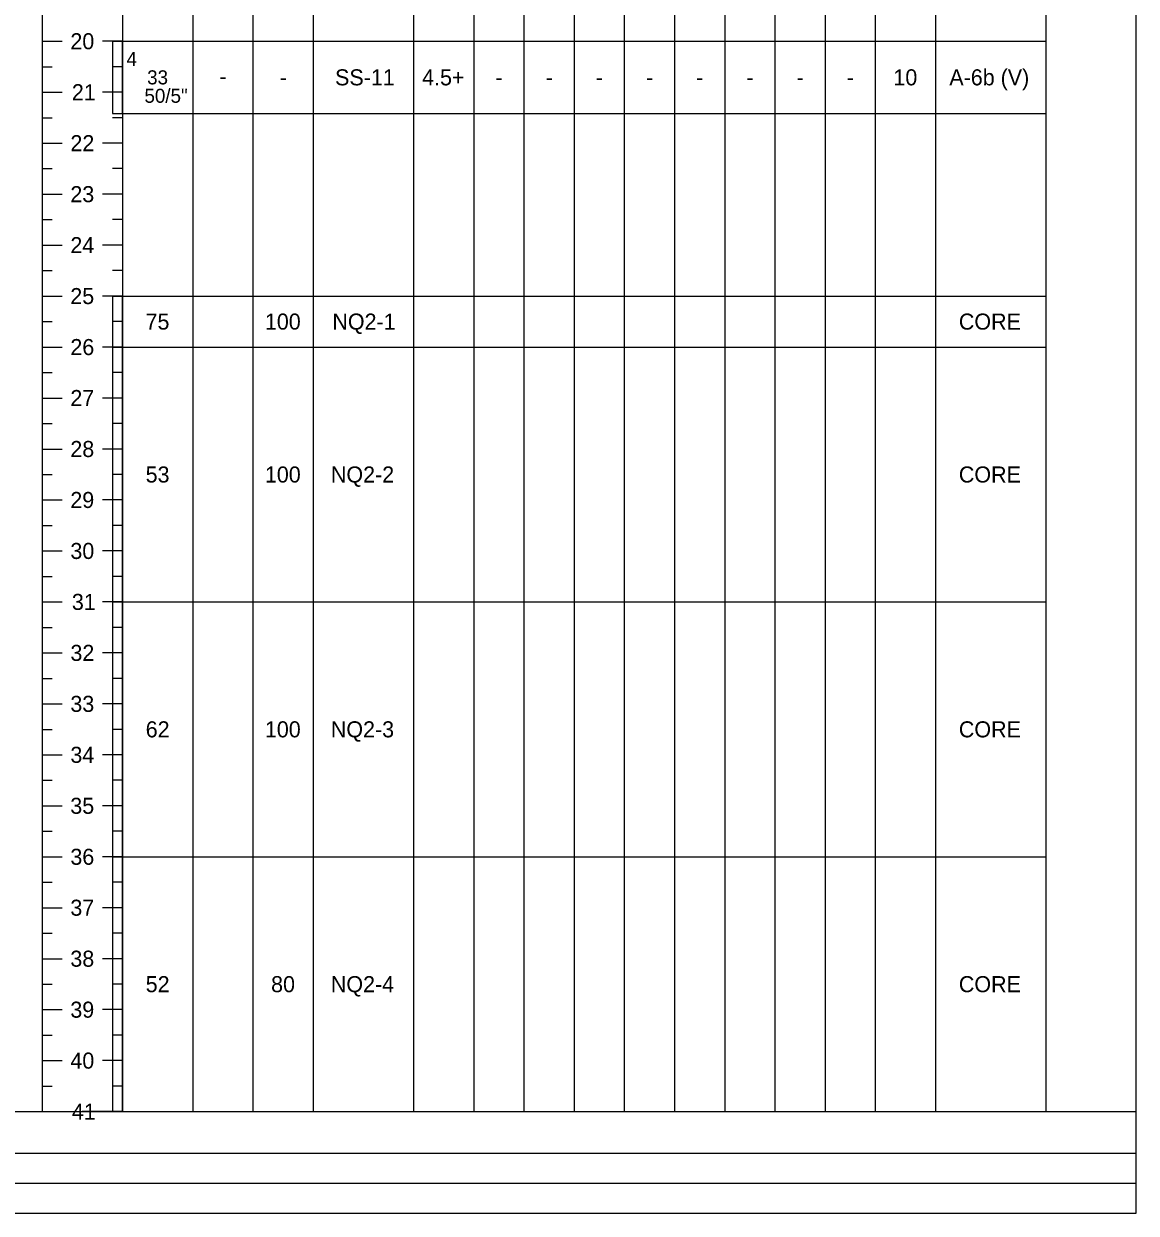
# Model space of a CAD drawing. Extents: x 0 to 0.833, y -0.381 to 0.608.
# Drawn here: x 0.3715 to 0.8333, y -0.3809 to 0.1131 of the extents above; entities that cross this region are included whole.
import ezdxf

# ---------------------------------------------------------------- set-up
doc = ezdxf.new("R2010")
doc.units = 0

msp = doc.modelspace()

# ---------------------------------------------------------------- linework, layer by layer
for points in [[(0, -0.38086), (0.83333, -0.38086), (0.83333, 0.60833), (0, 0.60833)], [(0.40833, 0.07585), (0.4125, 0.07585), (0.4125, 0.10583), (0.40833, 0.10583)], [(0.40833, -0.02117), (0.4125, -0.02117), (0.4125, 0), (0.40833, 0)], [(0.40833, -0.127), (0.4125, -0.127), (0.4125, -0.02117), (0.40833, -0.02117)], [(0.40833, -0.23283), (0.4125, -0.23283), (0.4125, -0.127), (0.40833, -0.127)], [(0.40833, -0.33867), (0.4125, -0.33867), (0.4125, -0.23283), (0.40833, -0.23283)]]:
    msp.add_lwpolyline(points, close=True)
for points in [[(0.4125, 0.55417), (0.4125, -0.33867)], [(0.4125, 0.55417), (0.4125, -0.33867)], [(0.44167, 0.55417), (0.44167, -0.33867)], [(0.46667, 0.55417), (0.46667, -0.33867)], [(0.49167, 0.55417), (0.49167, -0.33867)], [(0.53333, 0.55417), (0.53333, -0.33867)], [(0.55833, 0.55417), (0.55833, -0.33867)], [(0.6625, 0.55417), (0.6625, -0.33867)], [(0.725, 0.55417), (0.725, -0.33867)], [(0.75, 0.55417), (0.75, -0.33867)], [(0.75, 0.55417), (0.75, -0.33867)], [(0.79583, 0.55417), (0.79583, -0.33867)], [(0.57917, 0.54167), (0.57917, -0.33867)], [(0.6, 0.54167), (0.6, -0.33867)], [(0.62083, 0.54167), (0.62083, -0.33867)], [(0.64167, 0.54167), (0.64167, -0.33867)], [(0.68333, 0.54167), (0.68333, -0.33867)], [(0.70417, 0.54167), (0.70417, -0.33867)], [(0.725, 0.54167), (0.725, -0.33867)], [(0.37917, 0.52917), (0.37917, -0.33867)], [(0.37917, 0.10583), (0.3875, 0.10583)], [(0.37917, 0.10583), (0.38333, 0.10583)], [(0.4125, 0.10583), (0.40417, 0.10583)], [(0.40833, 0.10583), (0.40833, 0.07585)], [(0.40833, 0.10583), (0.4125, 0.10583)], [(0.4125, 0.10583), (0.40833, 0.10583)], [(0.4125, 0.10583), (0.44167, 0.10583)], [(0.44167, 0.10583), (0.46667, 0.10583)], [(0.46667, 0.10583), (0.49167, 0.10583)], [(0.49167, 0.10583), (0.53333, 0.10583)], [(0.53333, 0.10583), (0.55833, 0.10583)], [(0.55833, 0.10583), (0.57917, 0.10583)], [(0.57917, 0.10583), (0.6, 0.10583)], [(0.6, 0.10583), (0.62083, 0.10583)], [(0.62083, 0.10583), (0.64167, 0.10583)], [(0.64167, 0.10583), (0.6625, 0.10583)], [(0.6625, 0.10583), (0.68333, 0.10583)], [(0.68333, 0.10583), (0.70417, 0.10583)], [(0.70417, 0.10583), (0.725, 0.10583)], [(0.725, 0.10583), (0.75, 0.10583)], [(0.75, 0.10583), (0.79583, 0.10583)], [(0.37917, 0.09525), (0.38333, 0.09525)], [(0.4125, 0.09525), (0.40833, 0.09525)], [(0.37917, 0.08467), (0.3875, 0.08467)], [(0.37917, 0.08467), (0.38333, 0.08467)], [(0.4125, 0.08467), (0.40417, 0.08467)], [(0.4125, 0.08467), (0.40833, 0.08467)], [(0.40833, 0.07585), (0.4125, 0.07585)], [(0.4125, 0.07585), (0.44167, 0.07585)], [(0.44167, 0.07585), (0.46667, 0.07585)], [(0.46667, 0.07585), (0.49167, 0.07585)], [(0.49167, 0.07585), (0.53333, 0.07585)], [(0.53333, 0.07585), (0.55833, 0.07585)], [(0.55833, 0.07585), (0.57917, 0.07585)], [(0.57917, 0.07585), (0.6, 0.07585)], [(0.6, 0.07585), (0.62083, 0.07585)], [(0.62083, 0.07585), (0.64167, 0.07585)], [(0.64167, 0.07585), (0.6625, 0.07585)], [(0.6625, 0.07585), (0.68333, 0.07585)], [(0.68333, 0.07585), (0.70417, 0.07585)], [(0.70417, 0.07585), (0.725, 0.07585)], [(0.725, 0.07585), (0.75, 0.07585)], [(0.75, 0.07585), (0.79583, 0.07585)], [(0.37917, 0.07408), (0.38333, 0.07408)], [(0.4125, 0.07408), (0.40833, 0.07408)], [(0.37917, 0.0635), (0.3875, 0.0635)], [(0.37917, 0.0635), (0.38333, 0.0635)], [(0.4125, 0.0635), (0.40417, 0.0635)], [(0.4125, 0.0635), (0.40833, 0.0635)], [(0.37917, 0.05292), (0.38333, 0.05292)], [(0.4125, 0.05292), (0.40833, 0.05292)], [(0.37917, 0.04233), (0.3875, 0.04233)], [(0.37917, 0.04233), (0.38333, 0.04233)], [(0.4125, 0.04233), (0.40417, 0.04233)], [(0.4125, 0.04233), (0.40833, 0.04233)], [(0.37917, 0.03175), (0.38333, 0.03175)], [(0.4125, 0.03175), (0.40833, 0.03175)], [(0.37917, 0.02117), (0.3875, 0.02117)], [(0.37917, 0.02117), (0.38333, 0.02117)], [(0.4125, 0.02117), (0.40417, 0.02117)], [(0.4125, 0.02117), (0.40833, 0.02117)], [(0.37917, 0.01058), (0.38333, 0.01058)], [(0.4125, 0.01058), (0.40833, 0.01058)], [(0.37917, 0), (0.3875, 0)], [(0.37917, 0), (0.38333, 0)], [(0.4125, 0), (0.40417, 0)], [(0.40833, 0), (0.40833, -0.02117)], [(0.40833, 0), (0.4125, 0)], [(0.4125, 0), (0.40833, 0)], [(0.4125, 0), (0.44167, 0)], [(0.44167, 0), (0.46667, 0)], [(0.46667, 0), (0.49167, 0)], [(0.49167, 0), (0.53333, 0)], [(0.53333, 0), (0.55833, 0)], [(0.55833, 0), (0.57917, 0)], [(0.57917, 0), (0.6, 0)], [(0.6, 0), (0.62083, 0)], [(0.62083, 0), (0.64167, 0)], [(0.64167, 0), (0.6625, 0)], [(0.6625, 0), (0.68333, 0)], [(0.68333, 0), (0.70417, 0)], [(0.70417, 0), (0.725, 0)], [(0.725, 0), (0.75, 0)], [(0.75, 0), (0.79583, 0)], [(0.37917, -0.01058), (0.38333, -0.01058)], [(0.4125, -0.01058), (0.40833, -0.01058)], [(0.37917, -0.02117), (0.3875, -0.02117)], [(0.37917, -0.02117), (0.38333, -0.02117)], [(0.4125, -0.02117), (0.40417, -0.02117)], [(0.40833, -0.02117), (0.4125, -0.02117)], [(0.40833, -0.02117), (0.40833, -0.127)], [(0.40833, -0.02117), (0.4125, -0.02117)], [(0.4125, -0.02117), (0.40833, -0.02117)], [(0.4125, -0.02117), (0.44167, -0.02117)], [(0.44167, -0.02117), (0.46667, -0.02117)], [(0.46667, -0.02117), (0.49167, -0.02117)], [(0.49167, -0.02117), (0.53333, -0.02117)], [(0.53333, -0.02117), (0.55833, -0.02117)], [(0.55833, -0.02117), (0.57917, -0.02117)], [(0.57917, -0.02117), (0.6, -0.02117)], [(0.6, -0.02117), (0.62083, -0.02117)], [(0.62083, -0.02117), (0.64167, -0.02117)], [(0.64167, -0.02117), (0.6625, -0.02117)], [(0.6625, -0.02117), (0.68333, -0.02117)], [(0.68333, -0.02117), (0.70417, -0.02117)], [(0.70417, -0.02117), (0.725, -0.02117)], [(0.725, -0.02117), (0.75, -0.02117)], [(0.75, -0.02117), (0.79583, -0.02117)], [(0.37917, -0.03175), (0.38333, -0.03175)], [(0.4125, -0.03175), (0.40833, -0.03175)], [(0.37917, -0.04233), (0.3875, -0.04233)], [(0.37917, -0.04233), (0.38333, -0.04233)], [(0.4125, -0.04233), (0.40417, -0.04233)], [(0.4125, -0.04233), (0.40833, -0.04233)], [(0.37917, -0.05292), (0.38333, -0.05292)], [(0.4125, -0.05292), (0.40833, -0.05292)], [(0.37917, -0.0635), (0.3875, -0.0635)], [(0.37917, -0.0635), (0.38333, -0.0635)], [(0.4125, -0.0635), (0.40417, -0.0635)], [(0.4125, -0.0635), (0.40833, -0.0635)], [(0.37917, -0.07408), (0.38333, -0.07408)], [(0.4125, -0.07408), (0.40833, -0.07408)], [(0.37917, -0.08467), (0.3875, -0.08467)], [(0.37917, -0.08467), (0.38333, -0.08467)], [(0.4125, -0.08467), (0.40417, -0.08467)], [(0.4125, -0.08467), (0.40833, -0.08467)], [(0.37917, -0.09525), (0.38333, -0.09525)], [(0.4125, -0.09525), (0.40833, -0.09525)], [(0.37917, -0.10583), (0.3875, -0.10583)], [(0.37917, -0.10583), (0.38333, -0.10583)], [(0.4125, -0.10583), (0.40417, -0.10583)], [(0.4125, -0.10583), (0.40833, -0.10583)], [(0.37917, -0.11642), (0.38333, -0.11642)], [(0.4125, -0.11642), (0.40833, -0.11642)], [(0.37917, -0.127), (0.3875, -0.127)], [(0.37917, -0.127), (0.38333, -0.127)], [(0.4125, -0.127), (0.40417, -0.127)], [(0.40833, -0.127), (0.4125, -0.127)], [(0.40833, -0.127), (0.40833, -0.23283)], [(0.40833, -0.127), (0.4125, -0.127)], [(0.4125, -0.127), (0.40833, -0.127)], [(0.4125, -0.127), (0.44167, -0.127)], [(0.44167, -0.127), (0.46667, -0.127)], [(0.46667, -0.127), (0.49167, -0.127)], [(0.49167, -0.127), (0.53333, -0.127)], [(0.53333, -0.127), (0.55833, -0.127)], [(0.55833, -0.127), (0.57917, -0.127)], [(0.57917, -0.127), (0.6, -0.127)], [(0.6, -0.127), (0.62083, -0.127)], [(0.62083, -0.127), (0.64167, -0.127)], [(0.64167, -0.127), (0.6625, -0.127)], [(0.6625, -0.127), (0.68333, -0.127)], [(0.68333, -0.127), (0.70417, -0.127)], [(0.70417, -0.127), (0.725, -0.127)], [(0.725, -0.127), (0.75, -0.127)], [(0.75, -0.127), (0.79583, -0.127)], [(0.37917, -0.13758), (0.38333, -0.13758)], [(0.4125, -0.13758), (0.40833, -0.13758)], [(0.37917, -0.14817), (0.3875, -0.14817)], [(0.37917, -0.14817), (0.38333, -0.14817)], [(0.4125, -0.14817), (0.40417, -0.14817)], [(0.4125, -0.14817), (0.40833, -0.14817)], [(0.37917, -0.15875), (0.38333, -0.15875)], [(0.4125, -0.15875), (0.40833, -0.15875)], [(0.37917, -0.16933), (0.3875, -0.16933)], [(0.37917, -0.16933), (0.38333, -0.16933)], [(0.4125, -0.16933), (0.40417, -0.16933)], [(0.4125, -0.16933), (0.40833, -0.16933)], [(0.37917, -0.17992), (0.38333, -0.17992)], [(0.4125, -0.17992), (0.40833, -0.17992)], [(0.37917, -0.1905), (0.3875, -0.1905)], [(0.37917, -0.1905), (0.38333, -0.1905)], [(0.4125, -0.1905), (0.40417, -0.1905)], [(0.4125, -0.1905), (0.40833, -0.1905)], [(0.37917, -0.20108), (0.38333, -0.20108)], [(0.4125, -0.20108), (0.40833, -0.20108)], [(0.37917, -0.21167), (0.3875, -0.21167)], [(0.37917, -0.21167), (0.38333, -0.21167)], [(0.4125, -0.21167), (0.40417, -0.21167)], [(0.4125, -0.21167), (0.40833, -0.21167)], [(0.37917, -0.22225), (0.38333, -0.22225)], [(0.4125, -0.22225), (0.40833, -0.22225)], [(0.37917, -0.23283), (0.3875, -0.23283)], [(0.37917, -0.23283), (0.38333, -0.23283)], [(0.4125, -0.23283), (0.40417, -0.23283)], [(0.40833, -0.23283), (0.4125, -0.23283)], [(0.40833, -0.23283), (0.40833, -0.33867)], [(0.40833, -0.23283), (0.4125, -0.23283)], [(0.4125, -0.23283), (0.40833, -0.23283)], [(0.4125, -0.23283), (0.44167, -0.23283)], [(0.44167, -0.23283), (0.46667, -0.23283)], [(0.46667, -0.23283), (0.49167, -0.23283)], [(0.49167, -0.23283), (0.53333, -0.23283)], [(0.53333, -0.23283), (0.55833, -0.23283)], [(0.55833, -0.23283), (0.57917, -0.23283)], [(0.57917, -0.23283), (0.6, -0.23283)], [(0.6, -0.23283), (0.62083, -0.23283)], [(0.62083, -0.23283), (0.64167, -0.23283)], [(0.64167, -0.23283), (0.6625, -0.23283)], [(0.6625, -0.23283), (0.68333, -0.23283)], [(0.68333, -0.23283), (0.70417, -0.23283)], [(0.70417, -0.23283), (0.725, -0.23283)], [(0.725, -0.23283), (0.75, -0.23283)], [(0.75, -0.23283), (0.79583, -0.23283)], [(0.37917, -0.24342), (0.38333, -0.24342)], [(0.4125, -0.24342), (0.40833, -0.24342)], [(0.37917, -0.254), (0.3875, -0.254)], [(0.37917, -0.254), (0.38333, -0.254)], [(0.4125, -0.254), (0.40417, -0.254)], [(0.4125, -0.254), (0.40833, -0.254)], [(0.37917, -0.26458), (0.38333, -0.26458)], [(0.4125, -0.26458), (0.40833, -0.26458)], [(0, -0.26836), (0, -0.38086), (0.83333, -0.38086), (0.83333, -0.26836)], [(0.37917, -0.27517), (0.3875, -0.27517)], [(0.37917, -0.27517), (0.38333, -0.27517)], [(0.4125, -0.27517), (0.40417, -0.27517)], [(0.4125, -0.27517), (0.40833, -0.27517)], [(0.37917, -0.28575), (0.38333, -0.28575)], [(0.4125, -0.28575), (0.40833, -0.28575)], [(0.37917, -0.29633), (0.3875, -0.29633)], [(0.37917, -0.29633), (0.38333, -0.29633)], [(0.4125, -0.29633), (0.40417, -0.29633)], [(0.4125, -0.29633), (0.40833, -0.29633)], [(0.37917, -0.30692), (0.38333, -0.30692)], [(0.4125, -0.30692), (0.40833, -0.30692)], [(0.37917, -0.3175), (0.3875, -0.3175)], [(0.37917, -0.3175), (0.38333, -0.3175)], [(0.4125, -0.3175), (0.40417, -0.3175)], [(0.4125, -0.3175), (0.40833, -0.3175)], [(0.37917, -0.32808), (0.38333, -0.32808)], [(0.4125, -0.32808), (0.40833, -0.32808)], [(0.33333, -0.33867), (0.37917, -0.33867)], [(0.37917, -0.33867), (0.4125, -0.33867)], [(0.37917, -0.33867), (0.3875, -0.33867)], [(0.37917, -0.33867), (0.38333, -0.33867)], [(0.37917, -0.33867), (0.39583, -0.33867)], [(0.4125, -0.33867), (0.39583, -0.33867)], [(0.4125, -0.33867), (0.40417, -0.33867)], [(0.40833, -0.33867), (0.4125, -0.33867)], [(0.40833, -0.33867), (0.4125, -0.33867)], [(0.4125, -0.33867), (0.40833, -0.33867)], [(0.4125, -0.33867), (0.44167, -0.33867)], [(0.44167, -0.33867), (0.46667, -0.33867)], [(0.46667, -0.33867), (0.49167, -0.33867)], [(0.49167, -0.33867), (0.53333, -0.33867)], [(0.53333, -0.33867), (0.55833, -0.33867)], [(0.55833, -0.33867), (0.57917, -0.33867)], [(0.57917, -0.33867), (0.6, -0.33867)], [(0.6, -0.33867), (0.62083, -0.33867)], [(0.62083, -0.33867), (0.64167, -0.33867)], [(0.64167, -0.33867), (0.6625, -0.33867)], [(0.6625, -0.33867), (0.68333, -0.33867)], [(0.68333, -0.33867), (0.70417, -0.33867)], [(0.70417, -0.33867), (0.725, -0.33867)], [(0.725, -0.33867), (0.75, -0.33867)], [(0.75, -0.33867), (0.79583, -0.33867)], [(0.79583, -0.33867), (0.83333, -0.33867)], [(0, -0.35586), (0.83333, -0.35586)], [(0, -0.36836), (0.83333, -0.36836)]]:
    msp.add_lwpolyline(points)

# ---------------------------------------------------------------- texts
for s, height, p in [('20', 0.006667, (0.39088, 0.1025)), ('4', 0.00583, (0.41417, 0.09558)), ('SS-11', 0.006667, (0.50076, 0.08751)), ('4.5+', 0.006667, (0.5369, 0.08751)), ('10', 0.006667, (0.73254, 0.08751)), ('A-6b (V)', 0.006667, (0.75575, 0.08751)), ('33', 0.005833, (0.42274, 0.08792)), ('-', 0.00667, (0.45276, 0.08792)), ('-', 0.00667, (0.47776, 0.08751)), ('-', 0.00667, (0.56734, 0.08751)), ('-', 0.00667, (0.58818, 0.08751)), ('-', 0.00667, (0.60901, 0.08751)), ('-', 0.00667, (0.62984, 0.08751)), ('-', 0.00667, (0.65068, 0.08751)), ('-', 0.00667, (0.67151, 0.08751)), ('-', 0.00667, (0.69234, 0.08751)), ('-', 0.00667, (0.71318, 0.08751)), ('21', 0.006667, (0.39151, 0.08133)), ('50/5"', 0.005833, (0.42163, 0.08027)), ('22', 0.006667, (0.3909, 0.06017)), ('23', 0.006667, (0.39087, 0.039)), ('24', 0.006667, (0.39088, 0.01783)), ('25', 0.006667, (0.39084, -0.00333)), ('75', 0.006667, (0.42209, -0.01392)), ('100', 0.006667, (0.47162, -0.01392)), ('NQ2-1', 0.006667, (0.49964, -0.01392)), ('CORE', 0.006667, (0.75971, -0.01392)), ('26', 0.006667, (0.39087, -0.0245)), ('27', 0.006667, (0.39087, -0.04567)), ('28', 0.006667, (0.39086, -0.06683)), ('53', 0.006667, (0.42212, -0.07742)), ('100', 0.006667, (0.47162, -0.07742)), ('NQ2-2', 0.006667, (0.49903, -0.07742)), ('CORE', 0.006667, (0.75971, -0.07742)), ('29', 0.006667, (0.39086, -0.088)), ('30', 0.006667, (0.39088, -0.10917)), ('31', 0.006667, (0.39151, -0.13033)), ('32', 0.006667, (0.3909, -0.1515)), ('33', 0.006667, (0.39087, -0.17267)), ('62', 0.006667, (0.42215, -0.18325)), ('100', 0.006667, (0.47162, -0.18325)), ('NQ2-3', 0.006667, (0.499, -0.18325)), ('CORE', 0.006667, (0.75971, -0.18325)), ('34', 0.006667, (0.39088, -0.19383)), ('35', 0.006667, (0.39084, -0.215)), ('36', 0.006667, (0.39087, -0.23617)), ('37', 0.006667, (0.39087, -0.25733)), ('38', 0.006667, (0.39086, -0.2785)), ('52', 0.006667, (0.42215, -0.28908)), ('80', 0.006667, (0.47421, -0.28908)), ('NQ2-4', 0.006667, (0.49901, -0.28908)), ('CORE', 0.006667, (0.75971, -0.28908)), ('39', 0.006667, (0.39086, -0.29967)), ('40', 0.006667, (0.39088, -0.32083)), ('41', 0.006667, (0.39151, -0.342))]:
    msp.add_text(s, height=height).set_placement(p)

doc.saveas('drawing.dxf')
